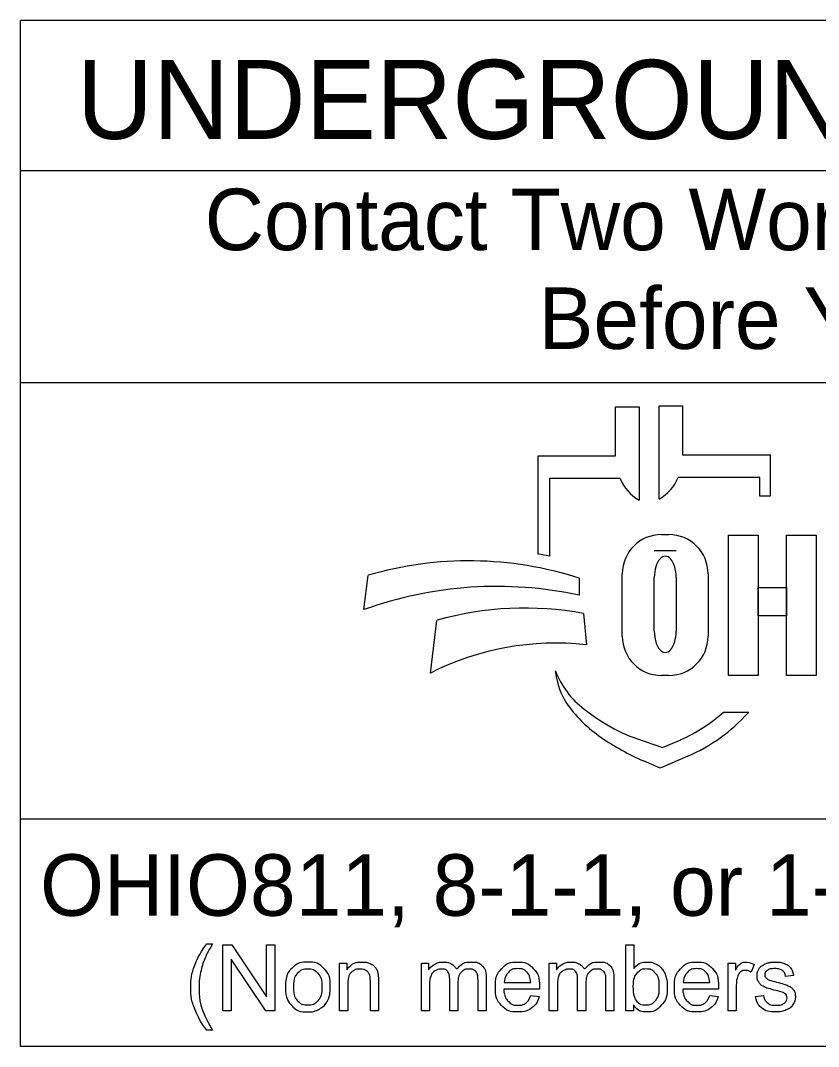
# Model space of a CAD drawing. Extents: x 0 to 34, y 0 to 22.
# Drawn here: x 2.378 to 4.196, y 2.143 to 4.48 of the extents above; entities that cross this region are included whole.
import ezdxf

# ---------------------------------------------------------------- set-up
doc = ezdxf.new("R2010")
doc.units = 0
doc.layers.add('SH_Data', color=7, linetype='Continuous')
doc.layers.add('SH_Text', color=7, linetype='Continuous')

msp = doc.modelspace()

# ---------------------------------------------------------------- linework, layer by layer
at = {"layer": 'SH_Data'}
for p, q in [((2.3775, 2.1428), (2.3775, 4.4803)), ((6.6275, 4.4803), (2.3775, 4.4803)), ((2.3775, 4.1387), (6.6275, 4.1387)), ((2.3775, 3.6553), (6.6275, 3.6553)), ((6.6275, 2.6607), (2.3775, 2.6607)), ((6.6275, 2.1428), (2.3775, 2.1428))]:
    msp.add_line(p, q, dxfattribs=at)
at = {"layer": 'SH_Text'}
for p, q in [((3.7335, 3.4883), (3.7335, 3.5998)), ((3.7335, 3.5998), (3.7872, 3.5998)), ((3.7872, 3.5998), (3.7872, 3.3877)), ((3.8329, 3.39), (3.8329, 3.6021)), ((3.8329, 3.6021), (3.8865, 3.6021)), ((3.8865, 3.6021), (3.8865, 3.4906)), ((3.5576, 3.2644), (3.5576, 3.4883)), ((3.5576, 3.4883), (3.7335, 3.4883)), ((3.8865, 3.4906), (4.0857, 3.4906)), ((4.0857, 3.4906), (4.0857, 3.3968)), ((3.5828, 3.4369), (3.5828, 3.26)), ((3.7439, 3.4369), (3.5828, 3.4369)), ((4.0625, 3.4392), (3.8761, 3.4392)), ((4.0625, 3.3968), (4.0625, 3.4392)), ((4.0857, 3.3968), (4.0625, 3.3968)), ((3.8385, 3.3091), (3.8551, 3.3091)), ((3.8718, 3.2721), (3.822, 3.2721)), ((3.1602, 3.1381), (3.1696, 3.2162)), ((3.6509, 3.2097), (3.6509, 3.1709)), ((3.7491, 3.0776), (3.7491, 3.2196)), ((3.822, 3.089), (3.822, 3.2114)), ((3.8718, 3.2114), (3.8718, 3.089)), ((3.9445, 3.2196), (3.9445, 3.0776)), ((3.312, 2.9936), (3.3267, 3.1137)), ((3.6608, 3.1291), (3.6671, 3.0582)), ((3.5997, 2.9807), (3.5967, 2.9986)), ((3.8551, 2.9882), (3.8385, 2.9882)), ((3.98, 2.9048), (4.0375, 2.9048)), ((3.7816, 2.8444), (3.841, 2.8239)), ((3.841, 2.8239), (3.8821, 2.8417)), ((3.835, 2.7769), (3.7976, 2.7934)), ((3.8983, 2.8044), (3.835, 2.7769))]:
    msp.add_line(p, q, dxfattribs=at)
for points in [[(3.991, 3.3081), (4.0589, 3.3081), (4.0589, 2.9881), (3.991, 2.9881)], [(4.1231, 3.3081), (4.1911, 3.3081), (4.1911, 2.9881), (4.1231, 2.9881)], [(4.0589, 3.1882), (4.1231, 3.1882), (4.1231, 3.1242), (4.0589, 3.1242)]]:
    msp.add_lwpolyline(points, close=True, dxfattribs=at)
for points in [[(2.8021, 2.3766), (2.8153, 2.3766)], [(2.8389, 2.2239), (2.8389, 2.3741), (2.8592, 2.3741), (2.9382, 2.2561), (2.9382, 2.3741), (2.9572, 2.3741), (2.9572, 2.2239), (2.9369, 2.2239), (2.8579, 2.3419), (2.8579, 2.2239), (2.8389, 2.2239)], [(3.7743, 2.2239), (3.7573, 2.2239), (3.7573, 2.3741), (3.7757, 2.3741), (3.7757, 2.3206)], [(3.1048, 2.2239), (3.1048, 2.3328), (3.1214, 2.3328), (3.1214, 2.3173)], [(3.2912, 2.2239), (3.2912, 2.3328), (3.3077, 2.3328), (3.3077, 2.3174)], [(3.5826, 2.2239), (3.5826, 2.3328), (3.5991, 2.3328), (3.5991, 2.3174)], [(3.9904, 2.2239), (3.9904, 2.3328), (4.007, 2.3328), (4.007, 2.3163)], [(4.0495, 2.3293), (4.043, 2.3122)], [(3.1932, 2.2908), (3.1932, 2.2239), (3.1748, 2.2239), (3.1748, 2.2901)], [(3.3743, 2.2871), (3.3743, 2.2239), (3.3559, 2.2239), (3.3559, 2.2946)], [(3.4388, 2.2986), (3.4388, 2.2239), (3.4203, 2.2239), (3.4203, 2.2924)], [(3.6657, 2.2871), (3.6657, 2.2239), (3.6473, 2.2239), (3.6473, 2.2946)], [(3.7301, 2.2986), (3.7301, 2.2239), (3.7117, 2.2239), (3.7117, 2.2924)], [(4.1394, 2.3046), (4.1213, 2.3022)], [(3.1233, 2.2833), (3.1233, 2.2239), (3.1048, 2.2239)], [(3.3097, 2.2803), (3.3097, 2.2239), (3.2912, 2.2239)], [(3.56, 2.2736), (3.4788, 2.2736)], [(3.4799, 2.2887), (3.5406, 2.2887)], [(3.601, 2.2803), (3.601, 2.2239), (3.5826, 2.2239)], [(3.968, 2.2736), (3.8868, 2.2736)], [(3.8879, 2.2887), (3.9486, 2.2887)], [(4.0088, 2.2809), (4.0088, 2.2239), (3.9904, 2.2239)], [(3.5404, 2.2591), (3.5595, 2.2567)], [(3.9484, 2.2591), (3.9675, 2.2567)], [(4.053, 2.2564), (4.0712, 2.2593)], [(3.7743, 2.2375), (3.7743, 2.2239)], [(2.8153, 2.1798), (2.8021, 2.1798)]]:
    msp.add_lwpolyline(points, dxfattribs=at)
for centre, radius, start, end in [((3.8353, 3.4736), 0.0985, 201.9296, 240.7469), ((3.7847, 3.476), 0.0985, 299.2531, 338.0704), ((3.8385, 3.2196), 0.0895, 90, 180), ((3.8551, 3.2196), 0.0895, 0, 90), ((3.3997, 2.4302), 0.8191, 72.1402, 106.3144), ((3.4295, 2.4554), 0.8191, 79.2074, 81.0007), ((3.4628, 2.2991), 0.8919, 77.8238, 109.8274), ((3.5267, 2.4094), 0.7322, 79.44, 105.8467), ((3.8385, 3.0776), 0.0895, 180, 270), ((3.8551, 3.0776), 0.0895, 270, 0), ((3.5987, 2.4262), 0.6357, 83.8248, 116.8021), ((3.7841, 3.0707), 0.2008, 201.0457, 232.5314), ((3.741, 3.0048), 0.1433, 189.6817, 216.0884), ((3.8747, 3.1022), 0.3088, 216.0884, 235.7167), ((3.9766, 3.3219), 0.5173, 232.5314, 241.794), ((3.7387, 3.1722), 0.3602, 293.4582, 312.0712), ((3.7387, 3.1722), 0.401, 293.4582, 317.8286), ((3.8914, 3.1631), 0.3371, 241.794, 250.9821), ((4.0412, 3.3465), 0.6044, 235.7167, 246.2325)]:
    msp.add_arc(centre, radius, start, end, dxfattribs=at)
for centre, start_param, end_param in [((3.8469, 3.2114), 4.712389, 7.853982), ((3.8469, 3.089), 1.570796, 4.712389)]:
    msp.add_ellipse(centre, major_axis=(0, 0.0484), ratio=0.514403, start_param=start_param, end_param=end_param, dxfattribs=at)
for points in [[(2.8021, 2.1798), (2.7869, 2.199), (2.7763, 2.2248), (2.7657, 2.2506), (2.7657, 2.2783), (2.7657, 2.3026), (2.7736, 2.325), (2.7829, 2.3509), (2.8021, 2.3766)], [(2.8153, 2.3766), (2.8029, 2.3553), (2.7989, 2.3462), (2.7927, 2.332), (2.7891, 2.3167), (2.7847, 2.2975), (2.7847, 2.2782), (2.7847, 2.2289), (2.8153, 2.1798)], [(2.9814, 2.2783), (2.9814, 2.3085), (2.9981, 2.3231), (3.0122, 2.3352), (3.0323, 2.3352), (3.0547, 2.3352), (3.069, 2.3205), (3.0832, 2.3058), (3.0832, 2.2799), (3.0832, 2.2589), (3.0769, 2.2469), (3.0706, 2.2348), (3.0586, 2.2282), (3.0466, 2.2215), (3.0323, 2.2215), (3.0095, 2.2215), (2.9954, 2.2362), (2.9814, 2.2508), (2.9814, 2.2783)], [(3.0003, 2.2783), (3.0003, 2.2574), (3.0094, 2.247), (3.0185, 2.2366), (3.0323, 2.2366), (3.046, 2.2366), (3.0551, 2.2471), (3.0642, 2.2575), (3.0642, 2.279), (3.0642, 2.2991), (3.0551, 2.3095), (3.0459, 2.3199), (3.0323, 2.3199), (3.0185, 2.3199), (3.0094, 2.3096), (3.0003, 2.2992), (3.0003, 2.2783)], [(3.1214, 2.3173), (3.1334, 2.3352), (3.156, 2.3352), (3.1659, 2.3352), (3.1741, 2.3316), (3.1823, 2.3281), (3.1864, 2.3224), (3.1905, 2.3166), (3.1922, 2.3087), (3.1932, 2.3036), (3.1932, 2.2908)], [(3.1748, 2.2901), (3.1748, 2.3013), (3.1726, 2.3069), (3.1705, 2.3125), (3.165, 2.3158), (3.1595, 2.3191), (3.1521, 2.3191), (3.1404, 2.3191), (3.1318, 2.3117), (3.1233, 2.3042), (3.1233, 2.2833)], [(3.3077, 2.3174), (3.3128, 2.3254), (3.3214, 2.3303), (3.3299, 2.3352), (3.3407, 2.3352), (3.3528, 2.3352), (3.3606, 2.3301), (3.3683, 2.3251), (3.3715, 2.3161), (3.3844, 2.3352), (3.4051, 2.3352), (3.4213, 2.3352), (3.43, 2.3262), (3.4388, 2.3172), (3.4388, 2.2986)], [(3.3559, 2.2946), (3.3559, 2.3069), (3.3514, 2.313), (3.3469, 2.3191), (3.3366, 2.3191), (3.3288, 2.3191), (3.3222, 2.315), (3.3156, 2.311), (3.3126, 2.3031), (3.3097, 2.2952), (3.3097, 2.2803)], [(3.4203, 2.2924), (3.4203, 2.3035), (3.4185, 2.3083), (3.4168, 2.3132), (3.412, 2.3162), (3.4073, 2.3191), (3.401, 2.3191), (3.3895, 2.3191), (3.3819, 2.3115), (3.3743, 2.3039), (3.3743, 2.2871)], [(3.5595, 2.2567), (3.555, 2.24), (3.5428, 2.2307), (3.5306, 2.2215), (3.5117, 2.2215), (3.4878, 2.2215), (3.4738, 2.2362), (3.4598, 2.2509), (3.4598, 2.2774), (3.4598, 2.3049), (3.474, 2.32), (3.4881, 2.3352), (3.5106, 2.3352), (3.5324, 2.3352), (3.5463, 2.3203), (3.5601, 2.3055), (3.5601, 2.2785), (3.5601, 2.2769), (3.56, 2.2736)], [(3.5406, 2.2887), (3.5394, 2.3025), (3.5337, 2.3094), (3.5249, 2.3201), (3.5108, 2.3201), (3.4981, 2.3201), (3.4894, 2.3115), (3.4808, 2.303), (3.4799, 2.2887)], [(3.5991, 2.3174), (3.6042, 2.3254), (3.6127, 2.3303), (3.6212, 2.3352), (3.6321, 2.3352), (3.6442, 2.3352), (3.6519, 2.3301), (3.6597, 2.3251), (3.6628, 2.3161), (3.6758, 2.3352), (3.6965, 2.3352), (3.7127, 2.3352), (3.7214, 2.3262), (3.7301, 2.3172), (3.7301, 2.2986)], [(3.6473, 2.2946), (3.6473, 2.3069), (3.6428, 2.313), (3.6383, 2.3191), (3.628, 2.3191), (3.6202, 2.3191), (3.6136, 2.315), (3.607, 2.311), (3.604, 2.3031), (3.601, 2.2952), (3.601, 2.2803)], [(3.7117, 2.2924), (3.7117, 2.3035), (3.7099, 2.3083), (3.7081, 2.3132), (3.7034, 2.3162), (3.6987, 2.3191), (3.6923, 2.3191), (3.6809, 2.3191), (3.6733, 2.3115), (3.6657, 2.3039), (3.6657, 2.2871)], [(3.7741, 2.2792), (3.7741, 2.2596), (3.7794, 2.2509), (3.7881, 2.2366), (3.8029, 2.2366), (3.815, 2.2366), (3.8238, 2.2471), (3.8326, 2.2576), (3.8326, 2.2784), (3.8326, 2.2998), (3.8241, 2.3099), (3.8157, 2.3201), (3.8038, 2.3201), (3.7917, 2.3201), (3.7829, 2.3096), (3.7741, 2.299), (3.7741, 2.2792)], [(3.7757, 2.3206), (3.7874, 2.3352), (3.8055, 2.3352), (3.8155, 2.3352), (3.8245, 2.3311), (3.8335, 2.3271), (3.8392, 2.3198), (3.845, 2.3124), (3.8483, 2.3021), (3.8516, 2.2918), (3.8516, 2.28), (3.8516, 2.252), (3.8378, 2.2368), (3.8239, 2.2215), (3.8046, 2.2215), (3.7853, 2.2215), (3.7743, 2.2375)], [(3.9675, 2.2567), (3.963, 2.24), (3.9508, 2.2307), (3.9386, 2.2215), (3.9196, 2.2215), (3.8958, 2.2215), (3.8818, 2.2362), (3.8678, 2.2509), (3.8678, 2.2774), (3.8678, 2.3049), (3.882, 2.32), (3.8961, 2.3352), (3.9186, 2.3352), (3.9404, 2.3352), (3.9543, 2.3203), (3.9681, 2.3055), (3.9681, 2.2785), (3.9681, 2.2769), (3.968, 2.2736)], [(3.9486, 2.2887), (3.9474, 2.3025), (3.9417, 2.3094), (3.9328, 2.3201), (3.9188, 2.3201), (3.9061, 2.3201), (3.8974, 2.3115), (3.8888, 2.303), (3.8879, 2.2887)], [(4.007, 2.3163), (4.0133, 2.3278), (4.0187, 2.3315), (4.0241, 2.3352), (4.0305, 2.3352), (4.0398, 2.3352), (4.0495, 2.3293)], [(4.043, 2.3122), (4.0363, 2.3162), (4.0295, 2.3162), (4.0235, 2.3162), (4.0187, 2.3125), (4.0139, 2.3089), (4.0119, 2.3024), (4.0088, 2.2926), (4.0088, 2.2809)], [(4.1213, 2.3022), (4.1201, 2.3106), (4.1142, 2.3153), (4.1083, 2.3201), (4.0975, 2.3201), (4.0848, 2.3201), (4.0794, 2.3159), (4.0739, 2.3116), (4.0739, 2.306), (4.0739, 2.3024), (4.0762, 2.2995), (4.0785, 2.2966), (4.0833, 2.2946), (4.086, 2.2936), (4.0996, 2.2899), (4.1192, 2.2847), (4.1269, 2.2813), (4.1347, 2.278), (4.1391, 2.2717), (4.1435, 2.2653), (4.1435, 2.2559), (4.1435, 2.2467), (4.1381, 2.2386), (4.1327, 2.2304), (4.1226, 2.226), (4.1124, 2.2215), (4.0996, 2.2215), (4.0784, 2.2215), (4.0672, 2.2303), (4.0561, 2.2391), (4.053, 2.2564)], [(4.0712, 2.2593), (4.0727, 2.2483), (4.0798, 2.2425), (4.0868, 2.2366), (4.0995, 2.2366), (4.1122, 2.2366), (4.1184, 2.2418), (4.1245, 2.247), (4.1245, 2.254), (4.1245, 2.2602), (4.1191, 2.2638), (4.1153, 2.2663), (4.1002, 2.2701), (4.0799, 2.2752), (4.072, 2.2789), (4.0642, 2.2827), (4.0601, 2.2893), (4.0561, 2.2959), (4.0561, 2.3038), (4.0561, 2.3111), (4.0594, 2.3173), (4.0628, 2.3235), (4.0685, 2.3276), (4.0728, 2.3308), (4.0803, 2.333), (4.0877, 2.3352), (4.0962, 2.3352), (4.109, 2.3352), (4.1187, 2.3315), (4.1284, 2.3278), (4.133, 2.3215), (4.1377, 2.3152), (4.1394, 2.3046)], [(3.4788, 2.2736), (3.4799, 2.2557), (3.489, 2.2462), (3.4981, 2.2366), (3.5117, 2.2366), (3.5219, 2.2366), (3.5291, 2.242), (3.5362, 2.2473), (3.5404, 2.2591)], [(3.8868, 2.2736), (3.8879, 2.2557), (3.897, 2.2462), (3.9061, 2.2366), (3.9197, 2.2366), (3.9299, 2.2366), (3.937, 2.242), (3.9442, 2.2473), (3.9484, 2.2591)]]:
    msp.add_open_spline(points, degree=3, dxfattribs=at)

# ---------------------------------------------------------------- texts
for s, height, p in [('UNDERGROUND UTILITIES', 0.18, (2.5057, 4.2106)), ('Contact Two Working Days', 0.14, (2.7972, 3.9571)), ('Before You Dig', 0.14, (3.5583, 3.7321)), ('OHIO811, 8-1-1, or 1-800-362-2764', 0.14, (2.422, 2.4406))]:
    msp.add_text(s, height=height, dxfattribs=at).set_placement(p)

doc.saveas('drawing.dxf')
